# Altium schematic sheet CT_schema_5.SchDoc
size 152 x 123 mm
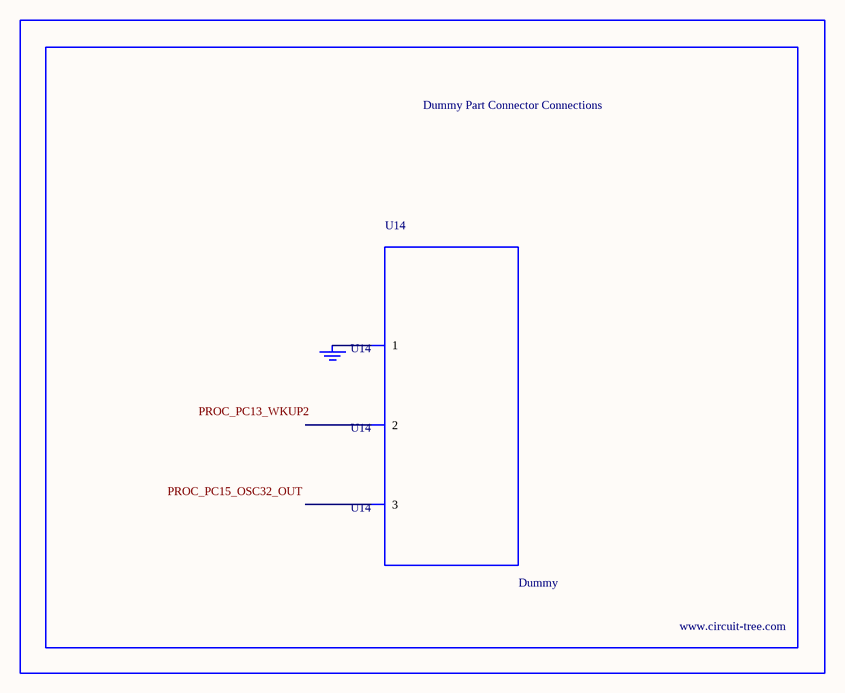
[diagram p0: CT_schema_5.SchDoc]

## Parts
BORDER4  (no value)
GND_INSTANCE_4_0  (no value)
U14  Dummy  [DUMMY_PACKAGE_110]

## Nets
NetGND_INSTANCE_4_0_0: GND_INSTANCE_4_0.0(GND) U14.1

Not connected (* = marked no-connect by the designer): U14 2 3

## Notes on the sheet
- Labels drawn without touching a wire or pin: PROC_PC13_WKUP2, PROC_PC15_OSC32_OUT

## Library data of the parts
BORDER4 = BORDER_PAGE4
GND_INSTANCE_4_0 = GND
